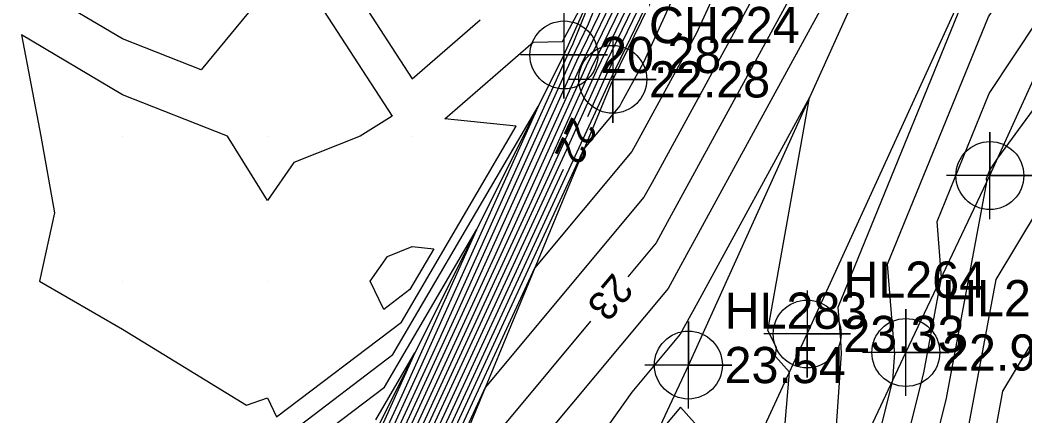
# Model space of a CAD drawing. Extents: x 2531902 to 2533249, y 715219 to 716099.
# Drawn here: x 2532842.9 to 2532912.3, y 715690.7 to 715718 of the extents above; entities that cross this region are included whole.
import ezdxf

# ---------------------------------------------------------------- set-up
doc = ezdxf.new("R2010")
doc.units = 0
for name, color, linetype in [('DTM Contours Major', 7, 'Continuous'), ('DTM Contours Major Text', 7, 'Continuous'), ('DTM Contours Minor', 7, 'Continuous'), ('Exist DTM Breakline', 7, 'Continuous'), ('Exist DTM Breakline Cogo Elevation', 7, 'Continuous'), ('Exist DTM Breakline Cogo Number', 7, 'Continuous'), ('Exist DTM Breakline Cogo Point CELL', 7, 'Continuous'), ('Exist DTM Crownline', 7, 'Continuous'), ('Exist DTM Crownline Cogo Elevation', 7, 'Continuous'), ('Exist DTM Crownline Cogo Number', 7, 'Continuous'), ('Exist DTM Crownline Cogo Point CELL', 7, 'Continuous'), ('Exist DTM QL2 LIDAR Elevation Point', 7, 'Continuous'), ('Exist Roads Soil', 7, 'Continuous'), ('Exist Roads Soil Cogo Elevation', 7, 'Continuous'), ('Exist Roads Soil Cogo Number', 7, 'Continuous'), ('Exist Roads Soil Cogo Point CELL', 7, 'Continuous')]:
    doc.layers.add(name, color=color, linetype=linetype)

msp = doc.modelspace()

# ---------------------------------------------------------------- linework, layer by layer
at = {"layer": 'DTM Contours Major'}
for points in [[(2532924.512, 715801.844), (2532922.712, 715798.378), (2532916.679, 715786.53), (2532909.832, 715771.258), (2532907.404, 715766.443), (2532903.158, 715756.872), (2532900.931, 715750.96), (2532890.629, 715729.59), (2532889.617, 715727.08), (2532883.368, 715714.157), (2532882.093, 715711.334)], [(2532926.402, 715790.98), (2532921.205, 715776.01), (2532917.456, 715766.943), (2532915.445, 715761.302), (2532907.4, 715743.928), (2532903.178, 715734.67), (2532899.089, 715725.845), (2532896.932, 715721.119), (2532887.609, 715704.047), (2532886.836, 715702.631), (2532884.884, 715700.293)], [(2532898.849, 715671.674), (2532899.305, 715677.659), (2532903.178, 715693.143), (2532903.312, 715695.057), (2532903.304, 715695.216), (2532902.827, 715701.162), (2532909.788, 715718.238), (2532918.296, 715731.087), (2532918.765, 715732.547), (2532920.73, 715735.312), (2532923.903, 715740.414), (2532930.869, 715758.95), (2532930.93, 715759.061), (2532933.351, 715763.754)], [(2532893.313, 715749.337), (2532899.157, 715757.294), (2532891.649, 715737.361), (2532888.467, 715730.76), (2532884.29, 715720.393), (2532881.681, 715715), (2532875.656, 715701.654), (2532869.225, 715687.729), (2532867.839, 715684.677), (2532864.865, 715678.232), (2532862.915, 715674.854)], [(2532880.417, 715707.702), (2532870.834, 715686.951)], [(2532833.041, 715658.953), (2532836.467, 715658.82), (2532841.725, 715659.565), (2532841.817, 715660.266), (2532842.154, 715668.099), (2532843.02, 715670.063), (2532851.032, 715677.56), (2532857.094, 715681.734), (2532861.988, 715687.097), (2532863.701, 715689.359), (2532868.079, 715692.676), (2532874.442, 715703.544), (2532869.274, 715692.097), (2532867.616, 715688.507), (2532865.522, 715683.895), (2532864.57, 715681.832), (2532859.473, 715672.999)], [(2532882.32, 715697.223), (2532873.621, 715686.805)]]:
    msp.add_lwpolyline(points, dxfattribs=at)
at = {"layer": 'DTM Contours Minor'}
for points in [[(2532887.602, 715731.228), (2532882.159, 715717.718), (2532881.007, 715715.337), (2532873.103, 715697.831), (2532868.581, 715688.041)], [(2532890.683, 715728.417), (2532883.705, 715713.988), (2532883.314, 715713.121), (2532871.155, 715686.796)], [(2532892.238, 715728.818), (2532885.975, 715715.09), (2532884.458, 715712.312), (2532884.332, 715712.082), (2532881.859, 715709.12), (2532871.477, 715686.64)], [(2532894.522, 715727.827), (2532889.628, 715717.099), (2532885.508, 715709.557), (2532885.167, 715708.931), (2532878.451, 715700.889), (2532871.799, 715686.484)], [(2532888.552, 715725.742), (2532883.031, 715714.326), (2532880.761, 715709.299), (2532870.512, 715687.107)], [(2532901.828, 715679.697), (2532905.323, 715693.676), (2532906.547, 715700.256), (2532906.237, 715704.117), (2532909.836, 715712.944), (2532918.233, 715725.627)], [(2532904.35, 715681.735), (2532906.894, 715691.911), (2532909.668, 715706.82), (2532909.647, 715707.072), (2532909.883, 715707.65), (2532910.432, 715708.479), (2532922.688, 715725.206)], [(2532887.486, 715724.405), (2532882.693, 715714.494), (2532879.485, 715707.387), (2532870.19, 715687.263)], [(2532898.871, 715683.97), (2532899.648, 715694.997), (2532899.601, 715695.909), (2532899.416, 715698.208), (2532909.741, 715723.533)], [(2532886.421, 715723.068), (2532882.356, 715714.663), (2532878.208, 715705.476), (2532869.868, 715687.418)], [(2532900.585, 715723.128), (2532888.659, 715701.292), (2532887.67, 715699.481), (2532879.396, 715689.571)], [(2532863.027, 715720), (2532868.614, 715711.386), (2532866.396, 715710), (2532861.828, 715708.172), (2532860, 715705.552), (2532857.234, 715710), (2532850, 715712.854), (2532843.01, 715716.99), (2532844.366, 715710), (2532845.301, 715704.699), (2532844.267, 715700), (2532850, 715696.674), (2532858.566, 715691.434), (2532860, 715691.942), (2532860.63, 715690.63), (2532869.256, 715697.164), (2532877.173, 715710.686), (2532872.252, 715711.205), (2532878.346, 715716.496), (2532880.374, 715716.527), (2532883.507, 715722.372), (2532881.093, 715716.381), (2532880.67, 715715.505), (2532871.827, 715695.92), (2532868.26, 715688.196)], [(2532885.355, 715721.73), (2532882.019, 715714.831), (2532876.932, 715703.565), (2532869.547, 715687.574)], [(2532859.886, 715720), (2532855.426, 715714.574), (2532850, 715716.715), (2532844.448, 715720)], [(2532866.084, 715720), (2532870, 715713.962), (2532874.687, 715718.032)], [(2532883.224, 715719.056), (2532881.344, 715715.168), (2532874.379, 715699.742), (2532868.903, 715687.885)], [(2532893.28, 715719.109), (2532886.559, 715706.802), (2532886.001, 715705.781), (2532875.044, 715692.658), (2532872.121, 715686.329)], [(2532895.21, 715683.963), (2532896.047, 715693.705), (2532895.073, 715694.795), (2532895.154, 715695.414), (2532894.543, 715696.584), (2532897.424, 715712.662), (2532889.71, 715698.537), (2532888.505, 715696.33), (2532885.17, 715692.337), (2532875.969, 715679.394)], [(2532910.037, 715688.381), (2532910.784, 715692.397), (2532922.922, 715712.526)], [(2532861.768, 715689.694), (2532868.668, 715694.92), (2532878.694, 715712.045), (2532870.55, 715694.009), (2532867.938, 715688.352)], [(2532908.466, 715690.146), (2532910.319, 715700.108), (2532916.168, 715709.807)], [(2532869.845, 715699.408), (2532868.045, 715698.045), (2532867.105, 715700), (2532868.295, 715701.705), (2532870, 715702.387), (2532871.497, 715702.23), (2532869.845, 715699.408)], [(2532867.491, 715690.431), (2532870.19, 715695.042), (2532867.998, 715690.186)], [(2532892.747, 715686.568), (2532888.516, 715691.302), (2532886.706, 715689.14)]]:
    msp.add_lwpolyline(points, dxfattribs=at)
at = {"layer": 'Exist DTM Breakline'}
for points in [[(2533029.092, 715973.615), (2533002.141, 715931.719), (2532981.109, 715895.925), (2532963.783, 715865.168), (2532944.31, 715831.075), (2532924.281, 715797.496), (2532904.489, 715756.171), (2532883.846, 715713.918), (2532865.559, 715669.748), (2532864.574, 715660.11), (2532866.15, 715657.26), (2532867.929, 715656.562)], [(2533023.854, 715972.817), (2532999.029, 715934.39), (2532976.745, 715897.826), (2532959.919, 715867.589), (2532939.765, 715833.591), (2532921.006, 715799.338), (2532899.767, 715758.656), (2532880.473, 715715.603), (2532864.431, 715683.527), (2532849.717, 715661.422)]]:
    msp.add_lwpolyline(points, dxfattribs=at)
at = {"layer": 'Exist DTM Breakline Cogo Point CELL'}
for points in [[(2532880.473, 715718.603), (2532880.473, 715712.603), (2532880.473, 715715.603), (2532883.473, 715715.603), (2532877.473, 715715.603)], [(2532883.846, 715716.918), (2532883.846, 715710.918), (2532883.846, 715713.918), (2532886.846, 715713.918), (2532880.846, 715713.918)]]:
    msp.add_lwpolyline(points, dxfattribs=at)
for centre in [(2532880.473, 715715.603), (2532883.846, 715713.918)]:
    msp.add_circle(centre, 2.344, dxfattribs=at)
at = {"layer": 'Exist DTM Crownline'}
msp.add_lwpolyline([(2532876.571, 715652.013), (2532884.036, 715667.726), (2532897.268, 715696.346), (2532912.052, 715728.687), (2532925.335, 715755.88), (2532939.894, 715784.74), (2532958.948, 715822.246), (2532974.275, 715850.523), (2532997.485, 715891.381), (2533017.87, 715925.252), (2533038.842, 715957.692)], dxfattribs=at)
at = {"layer": 'Exist DTM Crownline Cogo Point CELL'}
msp.add_lwpolyline([(2532897.268, 715699.346), (2532897.268, 715693.346), (2532897.268, 715696.346), (2532900.268, 715696.346), (2532894.268, 715696.346)], dxfattribs=at)
msp.add_circle((2532897.268, 715696.346), 2.344, dxfattribs=at)
at = {"layer": 'Exist DTM QL2 LIDAR Elevation Point'}
for p, q in [((2532850, 715710), (2532850, 715710)), ((2532860, 715710), (2532860, 715710)), ((2532870, 715710), (2532870, 715710)), ((2532850, 715700), (2532850, 715700)), ((2532860, 715700), (2532860, 715700)), ((2532870, 715700), (2532870, 715700))]:
    msp.add_line(p, q, dxfattribs=at)
at = {"layer": 'Exist Roads Soil'}
for points in [[(2533033.002, 715963.552), (2533014.441, 715935.484), (2532992.666, 715901.095), (2532976.471, 715871.314), (2532962.05, 715845.129), (2532943.271, 715807.995), (2532921.982, 715764.363), (2532902.685, 715724.284), (2532889.068, 715694.204), (2532879.255, 715673.169), (2532870.648, 715655.411), (2532876.571, 715652.013), (2532882.435, 715649.375)], [(2532882.435, 715649.375), (2532884.446, 715653.582), (2532893.832, 715673.236), (2532904.082, 715695.07), (2532909.886, 715707.279), (2532923.655, 715737.545), (2532935.371, 715761.586), (2532947.639, 715787.122), (2532960.723, 715812.473), (2532979.299, 715846.297), (2532995.343, 715875.457), (2533008.573, 715897.69), (2533027.701, 715928.616), (2533038.596, 715945.654), (2533044.798, 715955.275)]]:
    msp.add_lwpolyline(points, dxfattribs=at)
at = {"layer": 'Exist Roads Soil Cogo Point CELL'}
for points in [[(2532909.886, 715704.279), (2532909.886, 715710.279), (2532909.886, 715707.279), (2532912.886, 715707.279), (2532906.886, 715707.279)], [(2532904.082, 715692.07), (2532904.082, 715698.07), (2532904.082, 715695.07), (2532907.082, 715695.07), (2532901.082, 715695.07)], [(2532889.068, 715691.204), (2532889.068, 715697.204), (2532889.068, 715694.204), (2532892.068, 715694.204), (2532886.068, 715694.204)]]:
    msp.add_lwpolyline(points, dxfattribs=at)
for centre in [(2532909.886, 715707.279), (2532904.082, 715695.07), (2532889.068, 715694.204)]:
    msp.add_circle(centre, 2.344, dxfattribs=at)

# ---------------------------------------------------------------- texts
at = {"layer": 'DTM Contours Major Text'}
for s, rotation, p in [('22', 245.22719, (2532881.031, 715711.417)), ('23', 230.13803, (2532883.879, 715700.65))]:
    msp.add_text(s, height=2, rotation=rotation, dxfattribs=at).set_placement(p)
at = {"layer": 'Exist DTM Breakline Cogo Elevation'}
for s, p in [('20.28', (2532882.973, 715714.353)), ('22.28', (2532886.346, 715712.668))]:
    msp.add_text(s, height=2.5, dxfattribs=at).set_placement(p)
at = {"layer": 'Exist DTM Breakline Cogo Number'}
msp.add_text('CH224', height=2.5, dxfattribs=at).set_placement((2532886.346, 715716.418))
at = {"layer": 'Exist DTM Crownline Cogo Elevation'}
msp.add_text('23.33', height=2.5, dxfattribs=at).set_placement((2532899.768, 715695.096))
at = {"layer": 'Exist DTM Crownline Cogo Number'}
msp.add_text('HL264', height=2.5, dxfattribs=at).set_placement((2532899.768, 715698.846))
at = {"layer": 'Exist Roads Soil Cogo Elevation'}
for s, p in [('22.96', (2532906.582, 715693.82)), ('23.54', (2532891.568, 715692.954))]:
    msp.add_text(s, height=2.5, dxfattribs=at).set_placement(p)
at = {"layer": 'Exist Roads Soil Cogo Number'}
for s, p in [('HL289', (2532906.582, 715697.57)), ('HL283', (2532891.568, 715696.704))]:
    msp.add_text(s, height=2.5, dxfattribs=at).set_placement(p)

doc.saveas('drawing.dxf')
